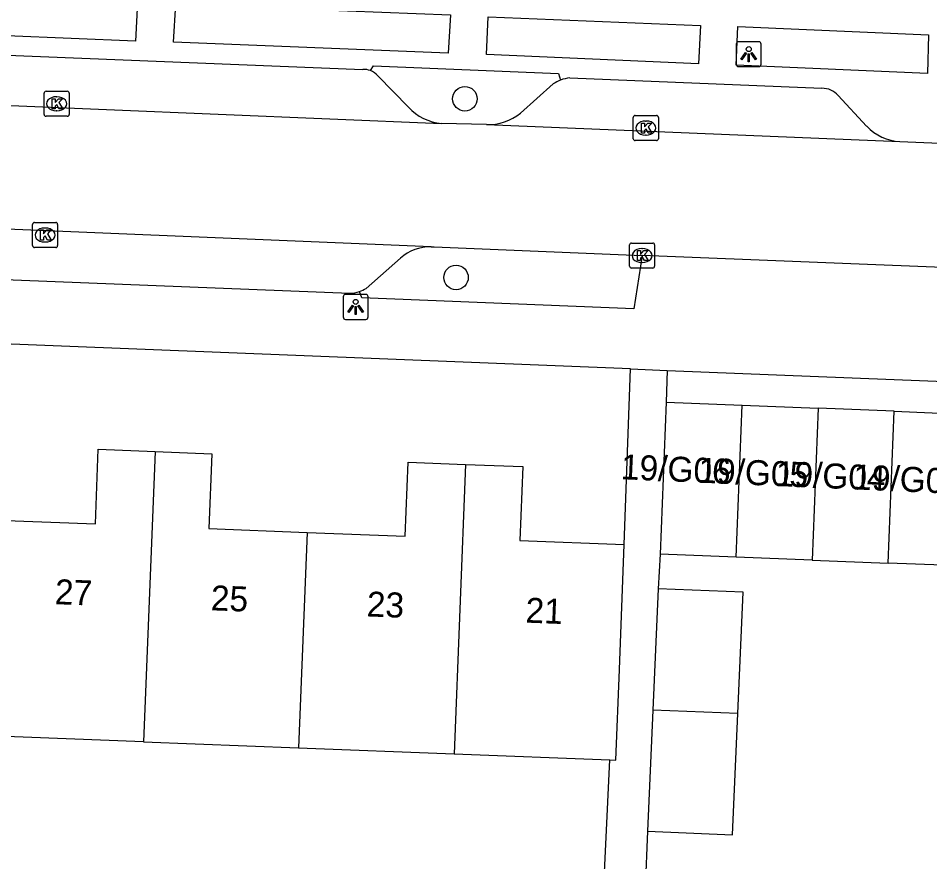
# Model space of a CAD drawing. Extents: x 161355 to 162026, y 386504 to 387459.
# Drawn here: x 161586.73 to 161623.15, y 387194.48 to 387228.21 of the extents above; entities that cross this region are included whole.
import ezdxf

# ---------------------------------------------------------------- set-up
doc = ezdxf.new("R2010")
doc.units = 0
for name, color, linetype in [('IMGEO_Boom', 7, 'Continuous'), ('IMGEO_Kolk', 7, 'Continuous'), ('IMGEO_Lichtpunt', 7, 'Continuous'), ('IMGEO_Pand', 7, 'Continuous'), ('IMGEO_Pand_nummerreeks', 7, 'Continuous'), ('IMGEO_Parkeervlak_open', 7, 'Continuous'), ('IMGEO_Rijbaan_lokaal_open', 7, 'Continuous'), ('IMGEO_Voetpad_open', 7, 'Continuous')]:
    doc.layers.add(name, color=color, linetype=linetype)

msp = doc.modelspace()

# ---------------------------------------------------------------- linework, layer by layer
at = {"layer": 'IMGEO_Boom'}
for centre in [(161604.578, 387224.987), (161604.225, 387217.844)]:
    msp.add_circle(centre, 0.489, dxfattribs=at)
at = {"layer": 'IMGEO_Kolk'}
for p, q in [((161587.767, 387224.363), (161587.767, 387225.215)), ((161587.842, 387225.289), (161588.694, 387225.289)), ((161588.768, 387225.215), (161588.768, 387224.363)), ((161588.255, 387225.069), (161588.28, 387225.069)), ((161588.278, 387224.509), (161588.253, 387224.509)), ((161588.694, 387224.289), (161587.842, 387224.289)), ((161611.309, 387223.393), (161611.309, 387224.245)), ((161611.384, 387224.319), (161612.236, 387224.319)), ((161611.797, 387224.099), (161611.822, 387224.099)), ((161612.31, 387224.245), (161612.31, 387223.393)), ((161612.236, 387223.319), (161611.384, 387223.319)), ((161611.82, 387223.539), (161611.795, 387223.539)), ((161587.378, 387220.042), (161588.23, 387220.042)), ((161587.303, 387219.116), (161587.303, 387219.968)), ((161587.791, 387219.822), (161587.816, 387219.822)), ((161588.304, 387219.968), (161588.304, 387219.116)), ((161588.23, 387219.042), (161587.378, 387219.042)), ((161587.814, 387219.262), (161587.789, 387219.262)), ((161611.158, 387218.294), (161611.158, 387219.146)), ((161611.233, 387219.22), (161612.085, 387219.22)), ((161611.646, 387219), (161611.671, 387219)), ((161612.159, 387219.146), (161612.159, 387218.294)), ((161612.085, 387218.22), (161611.233, 387218.22)), ((161611.669, 387218.44), (161611.644, 387218.44))]:
    msp.add_line(p, q, dxfattribs=at)
for points in [[(161587.767, 387224.363), (161587.767, 387225.215)], [(161587.842, 387225.289), (161588.694, 387225.289)], [(161588.768, 387225.215), (161588.768, 387224.363)], [(161588.088, 387224.989), (161588.211, 387224.989), (161588.211, 387224.838), (161588.341, 387224.989), (161588.505, 387224.989), (161588.359, 387224.838), (161588.512, 387224.589), (161588.36, 387224.589), (161588.275, 387224.753), (161588.211, 387224.686), (161588.211, 387224.589), (161588.088, 387224.589), (161588.088, 387224.989)], [(161588.694, 387224.289), (161587.842, 387224.289)], [(161611.309, 387223.393), (161611.309, 387224.245)], [(161611.384, 387224.319), (161612.236, 387224.319)], [(161612.31, 387224.245), (161612.31, 387223.393)], [(161611.63, 387224.019), (161611.753, 387224.019), (161611.753, 387223.868), (161611.883, 387224.019), (161612.047, 387224.019), (161611.901, 387223.868), (161612.054, 387223.619), (161611.902, 387223.619), (161611.817, 387223.783), (161611.753, 387223.716), (161611.753, 387223.619), (161611.63, 387223.619), (161611.63, 387224.019)], [(161612.236, 387223.319), (161611.384, 387223.319)], [(161587.378, 387220.042), (161588.23, 387220.042)], [(161587.303, 387219.116), (161587.303, 387219.968)], [(161587.624, 387219.742), (161587.747, 387219.742), (161587.747, 387219.591), (161587.877, 387219.742), (161588.041, 387219.742), (161587.895, 387219.591), (161588.048, 387219.342), (161587.896, 387219.342), (161587.811, 387219.506), (161587.747, 387219.439), (161587.747, 387219.342), (161587.624, 387219.342), (161587.624, 387219.742)], [(161588.304, 387219.968), (161588.304, 387219.116)], [(161588.23, 387219.042), (161587.378, 387219.042)], [(161611.158, 387218.294), (161611.158, 387219.146)], [(161611.233, 387219.22), (161612.085, 387219.22)], [(161612.159, 387219.146), (161612.159, 387218.294)], [(161611.479, 387218.92), (161611.602, 387218.92), (161611.602, 387218.769), (161611.732, 387218.92), (161611.896, 387218.92), (161611.75, 387218.769), (161611.903, 387218.52), (161611.751, 387218.52), (161611.666, 387218.684), (161611.602, 387218.617), (161611.602, 387218.52), (161611.479, 387218.52), (161611.479, 387218.92)], [(161612.085, 387218.22), (161611.233, 387218.22)]]:
    msp.add_lwpolyline(points, dxfattribs=at)
for centre, start, end in [((161587.844, 387225.213), 91.552, 178.448), ((161587.844, 387225.213), 91.552, 178.448), ((161588.692, 387225.213), 1.552, 88.448), ((161588.692, 387225.213), 1.552, 88.448), ((161587.844, 387224.365), 181.552, 268.448), ((161587.844, 387224.365), 181.552, 268.448), ((161588.692, 387224.365), 271.552, 358.448), ((161588.692, 387224.365), 271.552, 358.448), ((161611.386, 387224.243), 91.552, 178.448), ((161611.386, 387224.243), 91.552, 178.448), ((161612.234, 387224.243), 1.552, 88.448), ((161612.234, 387224.243), 1.552, 88.448), ((161611.386, 387223.395), 181.552, 268.448), ((161611.386, 387223.395), 181.552, 268.448), ((161612.234, 387223.395), 271.552, 358.448), ((161612.234, 387223.395), 271.552, 358.448), ((161587.38, 387219.966), 91.552, 178.448), ((161587.38, 387219.966), 91.552, 178.448), ((161588.228, 387219.966), 1.552, 88.448), ((161588.228, 387219.966), 1.552, 88.448), ((161587.38, 387219.118), 181.552, 268.448), ((161587.38, 387219.118), 181.552, 268.448), ((161588.228, 387219.118), 271.552, 358.448), ((161588.228, 387219.118), 271.552, 358.448), ((161611.235, 387219.144), 91.552, 178.448), ((161611.235, 387219.144), 91.552, 178.448), ((161612.083, 387219.144), 1.552, 88.448), ((161612.083, 387219.144), 1.552, 88.448), ((161611.235, 387218.296), 181.552, 268.448), ((161611.235, 387218.296), 181.552, 268.448), ((161612.083, 387218.296), 271.552, 358.448), ((161612.083, 387218.296), 271.552, 358.448)]:
    msp.add_arc(centre, 0.0765, start, end, dxfattribs=at)
for centre, major_axis, ratio, start_param, end_param in [((161588.254, 387224.789), (-0.387, 0.002), 0.722429, 4.712389, 7.853982), ((161588.279, 387224.789), (-0.39, 0.002), 0.717154, 1.570796, 4.712389), ((161611.796, 387223.819), (-0.387, 0.002), 0.722429, 4.712389, 7.853982), ((161611.821, 387223.819), (-0.39, 0.002), 0.717154, 1.570796, 4.712389), ((161587.79, 387219.542), (-0.387, 0.002), 0.722429, 4.712389, 7.853982), ((161587.815, 387219.542), (-0.39, 0.002), 0.717154, 1.570796, 4.712389), ((161611.645, 387218.72), (-0.387, 0.002), 0.722429, 4.712389, 7.853982), ((161611.67, 387218.72), (-0.39, 0.002), 0.717154, 1.570796, 4.712389)]:
    msp.add_ellipse(centre, major_axis=major_axis, ratio=ratio, start_param=start_param, end_param=end_param, dxfattribs=at)
at = {"layer": 'IMGEO_Lichtpunt'}
for p, q in [((161615.421, 387227.175), (161615.421, 387226.368)), ((161615.421, 387227.175), (161615.421, 387226.368)), ((161616.323, 387227.27), (161615.515, 387227.27)), ((161616.323, 387227.27), (161615.515, 387227.27)), ((161616.417, 387226.368), (161616.417, 387227.175)), ((161616.417, 387226.368), (161616.417, 387227.175)), ((161615.515, 387226.274), (161616.323, 387226.274)), ((161615.515, 387226.274), (161616.323, 387226.274)), ((161600.619, 387217.166), (161599.811, 387217.166)), ((161600.619, 387217.166), (161599.811, 387217.166)), ((161599.717, 387217.071), (161599.717, 387216.264)), ((161599.717, 387217.071), (161599.717, 387216.264)), ((161600.713, 387216.264), (161600.713, 387217.071)), ((161600.713, 387216.264), (161600.713, 387217.071)), ((161599.811, 387216.17), (161600.619, 387216.17)), ((161599.811, 387216.17), (161600.619, 387216.17))]:
    msp.add_line(p, q, dxfattribs=at)
for points in [[(161615.795, 387226.839), (161615.834, 387226.811), (161615.646, 387226.549), (161615.608, 387226.576), (161615.795, 387226.839)], [(161615.897, 387226.791), (161615.944, 387226.791), (161615.944, 387226.469), (161615.897, 387226.469), (161615.897, 387226.791)], [(161616.007, 387226.811), (161616.045, 387226.838), (161616.232, 387226.576), (161616.193, 387226.548), (161616.007, 387226.811)], [(161600.091, 387216.735), (161600.13, 387216.707), (161599.942, 387216.445), (161599.904, 387216.472), (161600.091, 387216.735)], [(161600.193, 387216.687), (161600.24, 387216.687), (161600.24, 387216.365), (161600.193, 387216.365), (161600.193, 387216.687)], [(161600.303, 387216.707), (161600.341, 387216.734), (161600.528, 387216.472), (161600.489, 387216.444), (161600.303, 387216.707)]]:
    msp.add_lwpolyline(points, dxfattribs=at)
for centre in [(161615.92, 387226.973), (161600.216, 387216.869)]:
    msp.add_circle(centre, 0.0994, dxfattribs=at)
for centre, start, end in [((161615.515, 387227.175), 90, 180), ((161615.515, 387227.175), 90, 180), ((161616.323, 387227.175), 0, 90), ((161616.323, 387227.175), 0, 90), ((161615.515, 387226.368), 180, 270), ((161615.515, 387226.368), 180, 270), ((161616.323, 387226.368), 270, 0), ((161616.323, 387226.368), 270, 360), ((161599.811, 387217.071), 90, 180), ((161599.811, 387217.071), 90, 180), ((161600.619, 387217.071), 0, 90), ((161600.619, 387217.071), 0, 90), ((161599.811, 387216.264), 180, 270), ((161599.811, 387216.264), 180, 270), ((161600.619, 387216.264), 270, 0), ((161600.619, 387216.264), 270, 360)]:
    msp.add_arc(centre, 0.0946, start, end, dxfattribs=at)
at = {"layer": 'IMGEO_Pand'}
for points in [[(161612.623, 387212.855), (161612.382, 387206.785)], [(161612.623, 387212.855), (161615.66, 387212.734)], [(161615.419, 387206.665), (161615.66, 387212.734)], [(161615.66, 387212.734), (161618.697, 387212.614)], [(161618.697, 387212.614), (161618.456, 387206.544)], [(161621.734, 387212.493), (161618.697, 387212.614)], [(161621.493, 387206.424), (161621.734, 387212.493)], [(161621.734, 387212.493), (161624.772, 387212.372)], [(161585.88, 387208.143), (161589.814, 387207.991), (161589.93, 387210.974), (161592.2, 387210.886)], [(161592.2, 387210.886), (161591.744, 387199.282)], [(161592.2, 387210.886), (161594.469, 387210.798), (161594.353, 387207.806), (161598.275, 387207.654)], [(161598.275, 387207.654), (161602.196, 387207.502), (161602.31, 387210.46), (161604.602, 387210.371)], [(161604.602, 387210.371), (161604.148, 387198.801)], [(161604.602, 387210.371), (161606.894, 387210.282), (161606.779, 387207.335), (161610.944, 387207.174)], [(161598.275, 387207.654), (161597.937, 387199.042)], [(161610.367, 387198.559), (161610.61, 387198.55), (161610.751, 387202.178), (161610.944, 387207.174)], [(161615.419, 387206.665), (161612.382, 387206.785)], [(161618.456, 387206.544), (161615.419, 387206.665)], [(161618.456, 387206.544), (161621.493, 387206.424)], [(161623.676, 387206.337), (161621.493, 387206.424)], [(161612.3, 387205.395), (161612.088, 387200.548)], [(161615.483, 387200.411), (161615.692, 387205.259), (161612.3, 387205.395)], [(161612.088, 387200.548), (161611.876, 387195.702)], [(161611.876, 387195.702), (161615.273, 387195.566), (161615.483, 387200.411)], [(161615.483, 387200.411), (161612.088, 387200.548)], [(161591.744, 387199.282), (161585.542, 387199.523)], [(161591.744, 387199.282), (161597.937, 387199.042)], [(161597.937, 387199.042), (161604.148, 387198.801)], [(161604.148, 387198.801), (161610.367, 387198.559)]]:
    msp.add_lwpolyline(points, dxfattribs=at)
at = {"layer": 'IMGEO_Parkeervlak_open'}
for points in [[(161602.323, 387224.649), (161601.105, 387225.909)], [(161608.11, 387225.588), (161606.807, 387224.416)], [(161600.634, 387217.408), (161602.005, 387218.615)]]:
    msp.add_lwpolyline(points, dxfattribs=at)
for centre, radius, start, end in [((161600.529, 387225.386), 0.778, 42.239, 69.1516), ((161608.891, 387224.415), 1.409, 110.2577, 123.6519), ((161603.817, 387226.032), 2.036, 222.7993, 265.0485), ((161605.485, 387226.082), 2.127, 268.7248, 308.4211), ((161603.213, 387217.247), 1.825, 89.5363, 131.4423), ((161599.979, 387218.423), 1.208, 288.8887, 302.844)]:
    msp.add_arc(centre, radius, start, end, dxfattribs=at)
at = {"layer": 'IMGEO_Rijbaan_lokaal_open'}
for points in [[(161581.321, 387224.933), (161603.641, 387224.004)], [(161605.438, 387223.956), (161603.641, 387224.004)], [(161605.438, 387223.956), (161621.964, 387223.274)], [(161621.964, 387223.274), (161626.421, 387223.099)], [(161603.228, 387219.072), (161581.145, 387219.987)], [(161603.228, 387219.072), (161603.35, 387219.067), (161611.659, 387218.72)], [(161632.346, 387217.886), (161632.019, 387217.909), (161611.659, 387218.72)]]:
    msp.add_lwpolyline(points, dxfattribs=at)
at = {"layer": 'IMGEO_Voetpad_open'}
for points in [[(161581.122, 387227.718), (161581.214, 387229.288), (161591.499, 387228.859), (161591.416, 387227.293), (161581.122, 387227.718)], [(161592.93, 387227.252), (161593.035, 387228.775), (161603.999, 387228.342), (161603.914, 387226.806), (161592.93, 387227.252)], [(161605.445, 387226.752), (161605.507, 387228.266), (161613.988, 387227.923), (161613.92, 387226.389), (161605.445, 387226.752)], [(161615.415, 387226.331), (161615.484, 387227.872), (161623.106, 387227.54), (161623.067, 387226.001), (161615.415, 387226.331)], [(161584.31, 387226.81), (161600.499, 387226.164)], [(161600.806, 387226.113), (161600.928, 387226.299), (161608.319, 387225.999), (161608.403, 387225.737)], [(161608.77, 387225.82), (161618.847, 387225.407)], [(161619.489, 387225.115), (161620.633, 387223.887)], [(161611.659, 387218.72), (161611.335, 387216.596), (161600.457, 387217.027), (161600.37, 387217.28)], [(161584.153, 387217.849), (161599.979, 387217.212)], [(161611.197, 387214.187), (161529.603, 387217.441)], [(161610.944, 387207.174), (161611.197, 387214.187)], [(161611.197, 387214.187), (161612.661, 387214.128)], [(161612.661, 387214.128), (161612.623, 387212.855)], [(161612.661, 387214.128), (161631.818, 387213.364)], [(161612.382, 387206.785), (161612.3, 387205.395)], [(161589.556, 387189.7), (161609.924, 387189.008), (161610.367, 387198.559)], [(161611.876, 387195.702), (161611.784, 387193.411)]]:
    msp.add_lwpolyline(points, dxfattribs=at)
for centre, radius, start, end in [((161600.527, 387225.386), 0.779, 69.0448, 92.091), ((161608.891, 387224.43), 1.395, 94.9933, 110.4937), ((161618.86, 387224.584), 0.823, 40.1641, 90.9211), ((161622.094, 387225.307), 2.037, 224.194, 266.3485), ((161599.968, 387218.436), 1.224, 270.5361, 289.1955)]:
    msp.add_arc(centre, radius, start, end, dxfattribs=at)

# ---------------------------------------------------------------- texts
at = {"layer": 'IMGEO_Pand_nummerreeks'}
for s, rotation, p in [('19/G06', 357.4937, (161610.797, 387209.78)), ('19/G05', 357.4937, (161613.891, 387209.645)), ('19/G04', 357.4937, (161616.985, 387209.51)), ('19/G03', 357.4937, (161620.078, 387209.374)), ('27', 357.7506, (161588.182, 387204.785)), ('25', 357.7506, (161594.413, 387204.54)), ('23', 357.7506, (161600.644, 387204.295)), ('21', 357.7483, (161606.988, 387204.047))]:
    msp.add_text(s, height=1, rotation=rotation, dxfattribs=at).set_placement(p)

doc.saveas('drawing.dxf')
